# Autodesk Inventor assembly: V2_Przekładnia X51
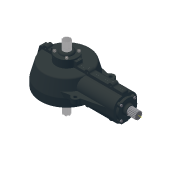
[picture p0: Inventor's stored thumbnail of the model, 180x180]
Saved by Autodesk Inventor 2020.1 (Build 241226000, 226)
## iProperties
Created: 2006-03
Part Number: V2_Przekładnia X51
Document SubType Name: Assembly
Designer: F.Stasiak
Project: Przekładnia X51
Description: Przekładnia X51
Manager: www.cadconsulting.pl
Company: Fabian Stasiak CAD Consulting
Author: F.Stasiak
Subject: Zbiór ćwiczeń. Autodesk Inventor 2020. Kurs podstawowy
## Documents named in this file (6)
- C:\2020_Kurs_podstawowy\R7 Prezentacje\V1_Przekładnia X51.iam
- C:\2020_Kurs_podstawowy\R7 Prezentacje\Komponenty\300-Wał_2.iam
- C:\2020_Kurs_podstawowy\R7 Prezentacje\Komponenty\300-Obudowa.iam
- C:\2020_Kurs_podstawowy\R7 Prezentacje\Komponenty\300-Wał_1.iam
- C:\2020_Kurs_podstawowy\Zasoby\Content Center Files\pl-PL\ISO 4762(2)\ISO 4762 - M5 x 12ISO.ipt
- C:\2020_Kurs_podstawowy\Zasoby\Content Center Files\pl-PL\DIN 7984\DIN 7984 - M5 x 12.ipt
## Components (15 placed, 5 different names)
1. 300-Obudowa:1 [sub-assembly]
2. 300-Wał_2:1 [sub-assembly]
3. 300-Wał_1:1 [sub-assembly]
4. ISO 4762 M5 x 12:1
5. ISO 4762 M5 x 12:2
6. ISO 4762 M5 x 12:3
7. ISO 4762 M5 x 12:4
8. DIN 7984 M5 x 12:1
9. DIN 7984 M5 x 12:2
10. DIN 7984 M5 x 12:3
11. DIN 7984 M5 x 12:4
12. ISO 4762 M5 x 12:5
13. ISO 4762 M5 x 12:6
14. ISO 4762 M5 x 12:7
15. ISO 4762 M5 x 12:8
## Named parameters: d82_d16 = 0
